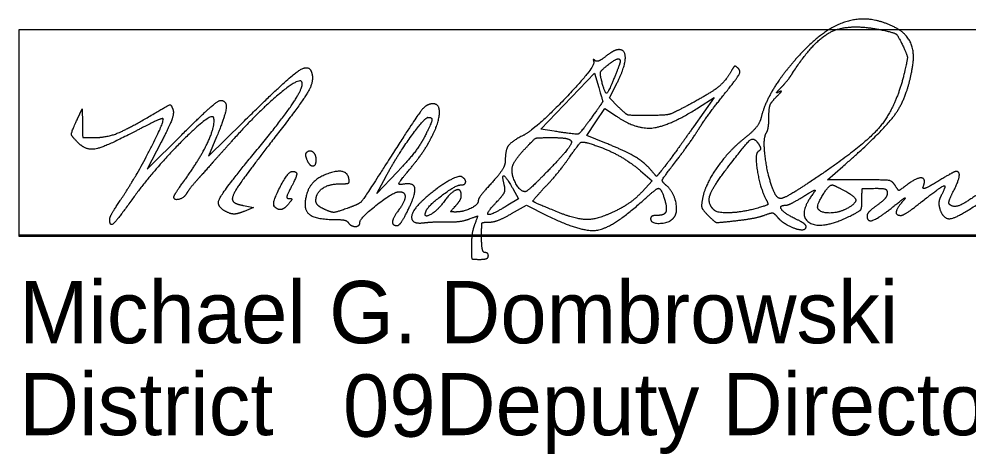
# Model space of a CAD drawing. Extents: x -13.1 to 43.1, y 0 to 22.
# Drawn here: x 25.119 to 27.252, y 9.145 to 10.123 of the extents above; entities that cross this region are included whole.
import ezdxf

# ---------------------------------------------------------------- set-up
doc = ezdxf.new("R2010")
doc.units = 0
doc.layers.add('SH_Data', color=7, linetype='Continuous')
doc.layers.add('SH_Text', color=7, linetype='Continuous')

msp = doc.modelspace()

# ---------------------------------------------------------------- linework, layer by layer
at = {"layer": 'SH_Data'}
msp.add_line((25.1191, 9.6377), (28.6191, 9.6377), dxfattribs=at)
msp.add_lwpolyline([(25.1191, 9.6343), (25.1191, 10.0991), (28.6231, 10.0991), (28.6231, 9.6343)], close=True, dxfattribs=at)
at = {"layer": 'SH_Text'}
for p, q in [((25.7663, 9.8073), (25.7663, 9.8073)), ((25.6931, 9.7015), (25.6931, 9.7015)), ((25.3229, 9.6732), (25.3229, 9.6732))]:
    msp.add_line(p, q, dxfattribs=at)
for points in [[(26.3223, 9.8707), (26.2919, 9.8755), (26.4128, 10.0012), (26.4223, 9.9691)], [(26.4662, 9.9256), (26.4463, 9.9455), (26.4622, 9.9766)], [(26.6467, 9.924), (26.6818, 9.9463), (26.635, 9.8802)], [(25.2504, 9.8982), (25.2609, 9.921), (25.2615, 9.8887)], [(26.4357, 9.8449), (26.3954, 9.8613), (26.4158, 9.8917), (26.4363, 9.922), (26.4621, 9.9044)], [(25.5633, 9.8581), (25.5453, 9.8146), (25.6223, 9.8906)], [(25.4388, 9.8461), (25.4075, 9.7855), (25.485, 9.8627)], [(25.9689, 9.7785), (25.9235, 9.731), (25.9443, 9.7696)], [(26.5161, 9.7819), (26.5427, 9.7589), (26.5199, 9.7348)], [(27.0085, 9.7614), (26.9363, 9.7614), (26.9711, 9.7918)], [(26.229, 9.7421), (26.2421, 9.7191), (26.2176, 9.7042)], [(25.6237, 9.7037), (25.6459, 9.6992), (25.6251, 9.6906)], [(26.2264, 9.6856), (26.2596, 9.7046), (26.3055, 9.6817)]]:
    msp.add_lwpolyline(points, dxfattribs=at)
for points in [[(27.0861, 10.105), (27.0292, 10.1334), (26.9239, 10.0993), (26.8662, 10.0338)], [(26.8581, 10.0014), (26.9052, 10.075), (26.9857, 10.1138), (27.0591, 10.0981)], [(27.0591, 10.0981), (27.0867, 10.0922), (27.0946, 10.0864), (27.1051, 10.0643)], [(27.1278, 10.016), (27.1332, 10.0488), (27.1132, 10.0915), (27.0861, 10.105)], [(26.4677, 10.054), (26.462, 10.054), (26.4488, 10.0472), (26.4383, 10.039)], [(26.4622, 9.9766), (26.4805, 10.0124), (26.4834, 10.054), (26.4677, 10.054)], [(27.1051, 10.0643), (27.1159, 10.0416), (27.1164, 10.0321), (27.1088, 10.0002)], [(26.411, 10.0267), (26.4146, 10.015), (26.2815, 9.8761), (26.2522, 9.8611)], [(26.4139, 10.0295), (26.4109, 10.0325), (26.4096, 10.0313), (26.411, 10.0267)], [(26.4383, 10.039), (26.4279, 10.0308), (26.4169, 10.0265), (26.4139, 10.0295)], [(26.4403, 10.0177), (26.4563, 10.0306), (26.4705, 10.0352), (26.4705, 10.0275)], [(26.4705, 10.0275), (26.4705, 10.0255), (26.465, 10.0101), (26.4583, 9.9933)], [(26.8662, 10.0338), (26.8326, 9.9956), (26.7947, 9.9318), (26.7871, 9.9007)], [(25.6223, 9.8906), (25.7167, 9.9838), (25.7692, 10.0227), (25.7761, 10.0047)], [(26.4289, 9.9835), (26.4249, 9.9996), (26.4274, 10.0073), (26.4403, 10.0177)], [(26.7204, 10.0064), (26.7073, 9.9831), (26.674, 9.9564), (26.6266, 9.9309)], [(26.7052, 9.9548), (26.7331, 9.9895), (26.742, 10.0059), (26.7361, 10.0117)], [(26.7361, 10.0117), (26.7303, 10.0174), (26.7257, 10.0159), (26.7204, 10.0064)], [(26.9711, 9.7918), (27.0633, 9.8724), (27.1167, 9.9488), (27.1278, 10.016)], [(25.7541, 9.9825), (25.7463, 9.9902), (25.6554, 9.9132), (25.6029, 9.8545)], [(25.7761, 10.0047), (25.783, 9.9867), (25.761, 9.9434), (25.7142, 9.883)], [(26.4583, 9.9933), (26.4439, 9.9575), (26.4361, 9.9549), (26.4289, 9.9835)], [(26.8315, 9.9682), (26.8398, 9.9766), (26.8518, 9.9916), (26.8581, 10.0014)], [(27.1088, 10.0002), (27.0899, 9.9216), (27.0134, 9.8336), (26.897, 9.7566)], [(25.661, 9.8374), (25.7152, 9.9028), (25.7615, 9.9751), (25.7541, 9.9825)], [(26.4223, 9.9691), (26.4314, 9.9381), (26.4309, 9.9357), (26.407, 9.9024)], [(26.8277, 9.959), (26.8214, 9.9556), (26.8231, 9.9598), (26.8315, 9.9682)], [(26.6469, 9.8755), (26.6574, 9.8922), (26.6836, 9.9279), (26.7052, 9.9548)], [(26.8048, 9.9036), (26.8048, 9.9227), (26.8104, 9.9371), (26.822, 9.9484)], [(26.822, 9.9484), (26.8314, 9.9575), (26.834, 9.9623), (26.8277, 9.959)], [(25.423, 9.9104), (25.456, 9.9298), (25.4608, 9.9308), (25.4651, 9.9195)], [(25.485, 9.8627), (25.5277, 9.9052), (25.5668, 9.94), (25.5719, 9.94)], [(25.5719, 9.94), (25.5866, 9.94), (25.583, 9.9057), (25.5633, 9.8581)], [(26.0491, 9.9324), (26.0351, 9.9324), (26.0092, 9.8988), (25.9415, 9.7927)], [(26.0441, 9.8525), (26.0629, 9.8881), (26.0656, 9.9324), (26.0491, 9.9324)], [(26.4621, 9.9044), (26.5063, 9.8742), (26.5806, 9.8821), (26.6467, 9.924)], [(26.5334, 9.906), (26.4923, 9.9058), (26.4834, 9.9084), (26.4662, 9.9256)], [(26.6266, 9.9309), (26.5892, 9.9108), (26.5719, 9.9062), (26.5334, 9.906)], [(25.2877, 9.8564), (25.3156, 9.8564), (25.3647, 9.8759), (25.423, 9.9104)], [(25.3503, 9.7207), (25.3801, 9.7649), (25.4472, 9.8942), (25.4426, 9.8987)], [(25.5571, 9.8999), (25.5538, 9.9167), (25.4202, 9.7833), (25.3707, 9.7139)], [(25.4426, 9.8987), (25.4411, 9.9003), (25.4142, 9.8881), (25.3829, 9.8717)], [(25.4651, 9.9195), (25.468, 9.9118), (25.4577, 9.8829), (25.4388, 9.8461)], [(25.4938, 9.764), (25.5267, 9.8098), (25.5604, 9.8824), (25.5571, 9.8999)], [(25.9443, 9.7696), (25.9687, 9.815), (26.031, 9.9018), (26.0392, 9.9019)], [(26.0392, 9.9019), (26.0487, 9.902), (26.0457, 9.8877), (26.0296, 9.8561)], [(26.407, 9.9024), (26.381, 9.8661), (26.372, 9.8628), (26.3223, 9.8707)], [(26.7871, 9.9007), (26.7844, 9.8896), (26.7683, 9.8695), (26.7514, 9.8561)], [(26.7984, 9.8656), (26.8019, 9.871), (26.8047, 9.8881), (26.8048, 9.9036)], [(25.252, 9.8447), (25.2369, 9.8599), (25.2366, 9.868), (25.2504, 9.8982)], [(25.2615, 9.8887), (25.2621, 9.8572), (25.2627, 9.8564), (25.2877, 9.8564)], [(25.7142, 9.883), (25.6365, 9.7826), (25.5962, 9.7243), (25.5989, 9.7162)], [(26.635, 9.8802), (26.6093, 9.8439), (26.581, 9.8049), (26.572, 9.7935)], [(25.3829, 9.8717), (25.3136, 9.8354), (25.2703, 9.8265), (25.252, 9.8447)], [(26.0296, 9.8561), (26.0212, 9.8396), (25.9938, 9.8047), (25.9689, 9.7785)], [(26.2522, 9.8611), (26.2255, 9.8475), (26.2121, 9.8282), (26.2121, 9.8035)], [(26.2535, 9.8279), (26.2771, 9.8535), (26.2835, 9.8564), (26.3176, 9.8564)], [(26.3176, 9.8564), (26.3385, 9.8564), (26.3577, 9.8529), (26.3604, 9.8486)], [(26.5949, 9.8021), (26.613, 9.8257), (26.6364, 9.8587), (26.6469, 9.8755)], [(26.7514, 9.8561), (26.7152, 9.8275), (26.6621, 9.7522), (26.6557, 9.7206)], [(26.8138, 9.7405), (26.8015, 9.772), (26.7914, 9.8544), (26.7984, 9.8656)], [(25.6029, 9.8545), (25.5722, 9.8202), (25.5368, 9.7806), (25.5243, 9.7665)], [(25.5933, 9.6862), (25.5606, 9.6987), (25.5777, 9.7368), (25.661, 9.8374)], [(25.9976, 9.7855), (26.0144, 9.8057), (26.0353, 9.8358), (26.0441, 9.8525)], [(26.3604, 9.8486), (26.363, 9.8443), (26.3421, 9.817), (26.314, 9.7878)], [(26.3567, 9.8127), (26.3769, 9.8416), (26.3852, 9.848), (26.3977, 9.8443)], [(26.3977, 9.8443), (26.4335, 9.8338), (26.4912, 9.8034), (26.5161, 9.7819)], [(26.539, 9.7841), (26.5253, 9.8005), (26.4818, 9.8262), (26.4357, 9.8449)], [(26.7118, 9.7888), (26.7545, 9.8448), (26.7717, 9.8577), (26.7819, 9.8414)], [(26.7819, 9.8414), (26.7863, 9.8343), (26.786, 9.8284), (26.7809, 9.8253)], [(25.7663, 9.8073), (25.7638, 9.8137), (25.7637, 9.8209), (25.766, 9.8233)], [(25.766, 9.8233), (25.7727, 9.8299), (25.7865, 9.8186), (25.7865, 9.8065)], [(26.2273, 9.784), (26.2273, 9.7924), (26.2391, 9.8122), (26.2535, 9.8279)], [(26.7809, 9.8253), (26.7726, 9.8201), (26.7849, 9.7432), (26.7982, 9.718)], [(25.7865, 9.8065), (25.7865, 9.7919), (25.772, 9.7925), (25.7663, 9.8073)], [(25.9415, 9.7927), (25.8939, 9.7181), (25.8839, 9.7069), (25.8566, 9.6972)], [(26.2121, 9.8035), (26.2121, 9.7948), (26.1984, 9.7728), (26.1817, 9.7546)], [(26.3044, 9.7481), (26.3192, 9.7637), (26.3427, 9.7928), (26.3567, 9.8127)], [(26.572, 9.7935), (26.5531, 9.7694), (26.5515, 9.769), (26.539, 9.7841)], [(26.5731, 9.7499), (26.5636, 9.7578), (26.5668, 9.7655), (26.5949, 9.8021)], [(25.6931, 9.7015), (25.6868, 9.7078), (25.7239, 9.7804), (25.7334, 9.7804)], [(25.7334, 9.7804), (25.744, 9.7804), (25.7427, 9.7679), (25.7293, 9.742)], [(25.8606, 9.7645), (25.8555, 9.7895), (25.7764, 9.7629), (25.767, 9.7331)], [(25.9803, 9.7513), (25.9711, 9.7496), (25.9764, 9.7601), (25.9976, 9.7855)], [(26.21, 9.7495), (26.204, 9.7724), (26.2139, 9.7685), (26.229, 9.7421)], [(26.2569, 9.7348), (26.247, 9.7348), (26.2273, 9.7676), (26.2273, 9.784)], [(26.314, 9.7878), (26.2858, 9.7586), (26.2601, 9.7348), (26.2569, 9.7348)], [(26.6808, 9.6942), (26.6663, 9.7087), (26.6781, 9.7446), (26.7118, 9.7888)], [(27.2256, 9.7804), (27.223, 9.7804), (27.2043, 9.7702), (27.1842, 9.7578)], [(27.2185, 9.7337), (27.2308, 9.7574), (27.2343, 9.7804), (27.2256, 9.7804)], [(25.4673, 9.7233), (25.4673, 9.7254), (25.4792, 9.7437), (25.4938, 9.764)], [(25.5243, 9.7665), (25.5117, 9.7525), (25.4988, 9.7362), (25.4954, 9.7303)], [(25.7865, 9.7144), (25.7865, 9.7318), (25.8157, 9.7525), (25.8401, 9.7525)], [(25.8401, 9.7525), (25.8571, 9.7525), (25.8625, 9.7557), (25.8606, 9.7645)], [(25.9934, 9.6933), (26.0117, 9.7309), (26.006, 9.7561), (25.9803, 9.7513)], [(26.1144, 9.7683), (26.107, 9.7728), (26.0499, 9.7376), (26.0235, 9.7122)], [(26.0344, 9.6919), (26.0392, 9.7037), (26.1012, 9.75), (26.1121, 9.75)], [(26.1121, 9.75), (26.1223, 9.75), (26.1239, 9.7624), (26.1144, 9.7683)], [(26.1817, 9.7546), (26.165, 9.7365), (26.1513, 9.7183), (26.1513, 9.7142)], [(26.1927, 9.7115), (26.2071, 9.7266), (26.2128, 9.739), (26.21, 9.7495)], [(26.5909, 9.6764), (26.6011, 9.6887), (26.5896, 9.7363), (26.5731, 9.7499)], [(26.897, 9.7566), (26.8662, 9.7362), (26.8367, 9.7196), (26.8314, 9.7196)], [(26.9152, 9.6966), (26.9112, 9.703), (26.9395, 9.75), (26.9473, 9.75)], [(26.9473, 9.75), (26.9488, 9.75), (26.9601, 9.7447), (26.9725, 9.7384)], [(27.0885, 9.7488), (27.0821, 9.759), (27.0672, 9.7614), (27.0085, 9.7614)], [(27.1171, 9.7516), (27.0982, 9.7376), (27.0957, 9.7374), (27.0885, 9.7488)], [(27.1516, 9.7457), (27.1586, 9.764), (27.1385, 9.7674), (27.1171, 9.7516)], [(27.1842, 9.7578), (27.164, 9.7455), (27.1494, 9.74), (27.1516, 9.7457)], [(27.3067, 9.7529), (27.2558, 9.7146), (27.2198, 9.6973), (27.2106, 9.7065)], [(25.4954, 9.7303), (25.4898, 9.7204), (25.4673, 9.7148), (25.4673, 9.7233)], [(25.7293, 9.742), (25.7214, 9.7268), (25.7205, 9.7196), (25.7264, 9.7196)], [(25.767, 9.7331), (25.7561, 9.699), (25.7833, 9.6724), (25.8292, 9.6724)], [(25.8853, 9.6657), (25.8853, 9.6755), (25.9611, 9.7348), (25.9737, 9.7348)], [(25.9737, 9.7348), (25.9873, 9.7348), (25.9866, 9.7121), (25.9724, 9.6934)], [(26.1133, 9.7259), (26.1133, 9.7425), (26.091, 9.7349), (26.0746, 9.7126)], [(26.3305, 9.6888), (26.2753, 9.711), (26.2734, 9.7154), (26.3044, 9.7481)], [(26.5199, 9.7348), (26.5073, 9.7215), (26.484, 9.7039), (26.4681, 9.6956)], [(26.5218, 9.715), (26.5385, 9.7301), (26.5539, 9.7424), (26.5562, 9.7424)], [(26.5562, 9.7424), (26.5628, 9.7424), (26.577, 9.6955), (26.5725, 9.6883)], [(26.8314, 9.7196), (26.8262, 9.7196), (26.8183, 9.729), (26.8138, 9.7405)], [(26.8829, 9.7246), (26.9006, 9.7358), (26.9113, 9.74), (26.9068, 9.7341)], [(26.9068, 9.7341), (26.868, 9.684), (26.9218, 9.648), (26.9873, 9.6802)], [(26.9725, 9.7384), (26.9983, 9.725), (27.0014, 9.7084), (26.9802, 9.697)], [(27.0139, 9.7159), (27.0139, 9.7411), (27.0156, 9.7424), (27.0481, 9.7424)], [(27.0481, 9.7424), (27.0628, 9.7424), (27.0709, 9.7385), (27.0709, 9.7315)], [(27.0709, 9.7315), (27.0709, 9.7255), (27.0606, 9.7133), (27.0481, 9.7044)], [(27.1478, 9.712), (27.1904, 9.7457), (27.205, 9.7505), (27.1923, 9.7269)], [(27.2106, 9.7065), (27.2084, 9.7087), (27.2119, 9.721), (27.2185, 9.7337)], [(25.3229, 9.6732), (25.3229, 9.677), (25.3352, 9.6983), (25.3503, 9.7207)], [(25.3707, 9.7139), (25.3394, 9.6701), (25.3229, 9.656), (25.3229, 9.6732)], [(25.5989, 9.7162), (25.6003, 9.7118), (25.6115, 9.7061), (25.6237, 9.7037)], [(25.7257, 9.7082), (25.7159, 9.6963), (25.7013, 9.6933), (25.6931, 9.7015)], [(25.7264, 9.7196), (25.7327, 9.7196), (25.7325, 9.7163), (25.7257, 9.7082)], [(25.806, 9.6951), (25.7953, 9.7), (25.7865, 9.7087), (25.7865, 9.7144)], [(26.0235, 9.7122), (25.9999, 9.6895), (26.0035, 9.6616), (26.0297, 9.6651)], [(26.0746, 9.7126), (26.0584, 9.6907), (26.0273, 9.6747), (26.0344, 9.6919)], [(26.1513, 9.7142), (26.1513, 9.7055), (26.118, 9.6892), (26.1003, 9.6892)], [(26.1007, 9.7031), (26.1076, 9.7107), (26.1133, 9.721), (26.1133, 9.7259)], [(26.2176, 9.7042), (26.1804, 9.6815), (26.1675, 9.6853), (26.1927, 9.7115)], [(26.3055, 9.6817), (26.383, 9.6429), (26.4542, 9.6539), (26.5218, 9.715)], [(26.6557, 9.7206), (26.6524, 9.7038), (26.6555, 9.6942), (26.6682, 9.6815)], [(26.7982, 9.718), (26.8038, 9.7074), (26.8, 9.7037), (26.7765, 9.6972)], [(26.8424, 9.7044), (26.847, 9.7044), (26.8653, 9.7135), (26.8829, 9.7246)], [(26.9873, 9.6802), (27.0088, 9.6908), (27.0139, 9.6976), (27.0139, 9.7159)], [(27.0853, 9.7021), (27.1045, 9.7176), (27.1143, 9.7233), (27.107, 9.7148)], [(27.107, 9.7148), (27.0922, 9.6976), (27.0895, 9.6816), (27.1015, 9.6816)], [(27.1015, 9.6816), (27.1058, 9.6816), (27.1266, 9.6952), (27.1478, 9.712)], [(27.1923, 9.7269), (27.1878, 9.7184), (27.1862, 9.7047), (27.1888, 9.6965)], [(27.1888, 9.6965), (27.1968, 9.6711), (27.232, 9.678), (27.2874, 9.716)], [(25.6251, 9.6906), (25.6136, 9.6859), (25.5993, 9.6839), (25.5933, 9.6862)], [(25.8566, 9.6972), (25.8321, 9.6885), (25.8215, 9.6881), (25.806, 9.6951)], [(25.9724, 9.6934), (25.9596, 9.6764), (25.9578, 9.6588), (25.969, 9.6588)], [(25.969, 9.6588), (25.9732, 9.6588), (25.9842, 9.6743), (25.9934, 9.6933)], [(26.1003, 9.6892), (26.0893, 9.6892), (26.0893, 9.6904), (26.1007, 9.7031)], [(26.176, 9.6665), (26.1854, 9.6665), (26.2081, 9.6751), (26.2264, 9.6856)], [(26.4681, 9.6956), (26.4248, 9.6734), (26.375, 9.6709), (26.3305, 9.6888)], [(26.5725, 9.6883), (26.5703, 9.6846), (26.5617, 9.6816), (26.5536, 9.6816)], [(26.7765, 9.6972), (26.7443, 9.6883), (26.6884, 9.6865), (26.6808, 9.6942)], [(26.7951, 9.6822), (26.8094, 9.6876), (26.8166, 9.6868), (26.8229, 9.6789)], [(26.864, 9.674), (26.84, 9.6853), (26.8264, 9.7044), (26.8424, 9.7044)], [(26.9802, 9.697), (26.9616, 9.6871), (26.9212, 9.6868), (26.9152, 9.6966)], [(27.0481, 9.7044), (27.0355, 9.6954), (27.0253, 9.6849), (27.0253, 9.681)], [(27.0253, 9.681), (27.0253, 9.6659), (27.0519, 9.6752), (27.0853, 9.7021)], [(25.8292, 9.6724), (25.8434, 9.6724), (25.8568, 9.6694), (25.8592, 9.6656)], [(25.8592, 9.6656), (25.8647, 9.6567), (25.8853, 9.6567), (25.8853, 9.6657)], [(26.0297, 9.6651), (26.0401, 9.6664), (26.063, 9.6673), (26.0804, 9.6669)], [(26.0804, 9.6669), (26.0979, 9.6666), (26.1208, 9.6696), (26.1314, 9.6736)], [(26.1314, 9.6736), (26.1497, 9.6806), (26.1503, 9.68), (26.1434, 9.6618)], [(26.1589, 9.6322), (26.1589, 9.6625), (26.1608, 9.6664), (26.176, 9.6665)], [(26.5536, 9.6816), (26.5455, 9.6816), (26.5389, 9.6781), (26.5389, 9.674)], [(26.5389, 9.674), (26.5389, 9.6628), (26.5813, 9.6647), (26.5909, 9.6764)], [(26.6682, 9.6815), (26.6833, 9.6664), (26.6899, 9.6651), (26.7305, 9.6697)], [(26.7305, 9.6697), (26.7555, 9.6726), (26.7846, 9.6782), (26.7951, 9.6822)], [(26.8229, 9.6789), (26.8276, 9.673), (26.8383, 9.6645), (26.8467, 9.6599)], [(26.8883, 9.6569), (26.8882, 9.66), (26.8773, 9.6677), (26.864, 9.674)], [(26.1434, 9.6618), (26.1394, 9.6512), (26.1361, 9.6291), (26.1361, 9.6127)], [(26.8467, 9.6599), (26.8643, 9.6503), (26.8886, 9.6485), (26.8883, 9.6569)], [(26.1665, 9.598), (26.1623, 9.598), (26.1589, 9.6134), (26.1589, 9.6322)], [(26.1361, 9.6127), (26.1361, 9.5858), (26.138, 9.5828), (26.1551, 9.5828)], [(26.1551, 9.5828), (26.1655, 9.5828), (26.1741, 9.5862), (26.1741, 9.5904)], [(26.1741, 9.5904), (26.1741, 9.5945), (26.1707, 9.598), (26.1665, 9.598)]]:
    msp.add_open_spline(points, degree=2, dxfattribs=at)

# ---------------------------------------------------------------- texts
for s, p in [('Michael G. Dombrowski', (25.1191, 9.3943)), ('District       Deputy Director', (25.1191, 9.1877)), ('              09', (25.1191, 9.1843))]:
    msp.add_text(s, height=0.14, dxfattribs=at).set_placement(p)

doc.saveas('drawing.dxf')
